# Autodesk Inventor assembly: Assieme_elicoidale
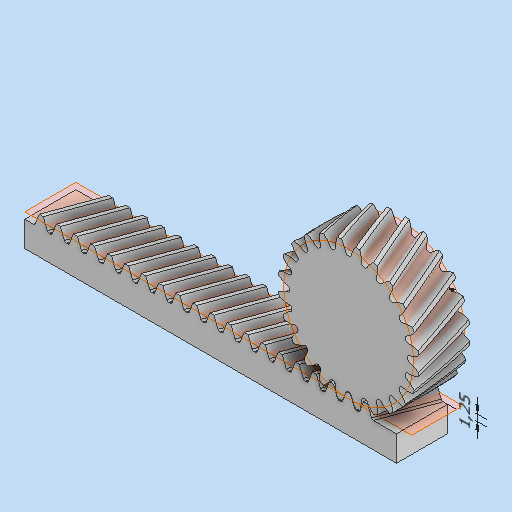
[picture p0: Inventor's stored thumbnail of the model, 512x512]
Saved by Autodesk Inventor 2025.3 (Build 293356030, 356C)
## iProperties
Created: 2025-12
Part Number: Assieme_elicoidale
Document SubType Name: Assembly
Designer: R5800u
Author: R5800u
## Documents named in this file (5)
- C:\Users\R5800u\Desktop\gripper_MGN7C\Assieme_elicoidale.iam
- C:\Users\R5800u\Desktop\gripper_MGN7C\cremagliera_elicoidale.ipt
- C:\Users\R5800u\Desktop\gripper_MGN7C\pignone_elicoidale_inv2.ipt
- C:\Users\R5800u\Desktop\gripper_MGN7C\Ingranaggio cilindrico11.ipt
- C:\Users\R5800u\Desktop\gripper_MGN7C\pignone_elicoidale2.ipt
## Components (4 placed, 3 different names)
1. cremagliera_elicoidale:1 — Allineato:1, Tangente:1, Allineato:2, Angolo:1
2. Ingranaggio cilindrico1:1
3. Ingranaggio cilindrico1:2 — Allineato:1
4. pignone_elicoidale2:1 — Tangente:1, Allineato:2, Angolo:1
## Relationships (4: Flush 2, Tangent 1, Angle 1)
- Allineato:1 [Flush]: cremagliera_elicoidale:1 ↔ Ingranaggio cilindrico1:2
- Tangente:1: cremagliera_elicoidale:1 ↔ pignone_elicoidale2:1
- Allineato:2 [Flush]: cremagliera_elicoidale:1 ↔ pignone_elicoidale2:1
- Angolo:1 [Angle]: cremagliera_elicoidale:1 ↔ pignone_elicoidale2:1
